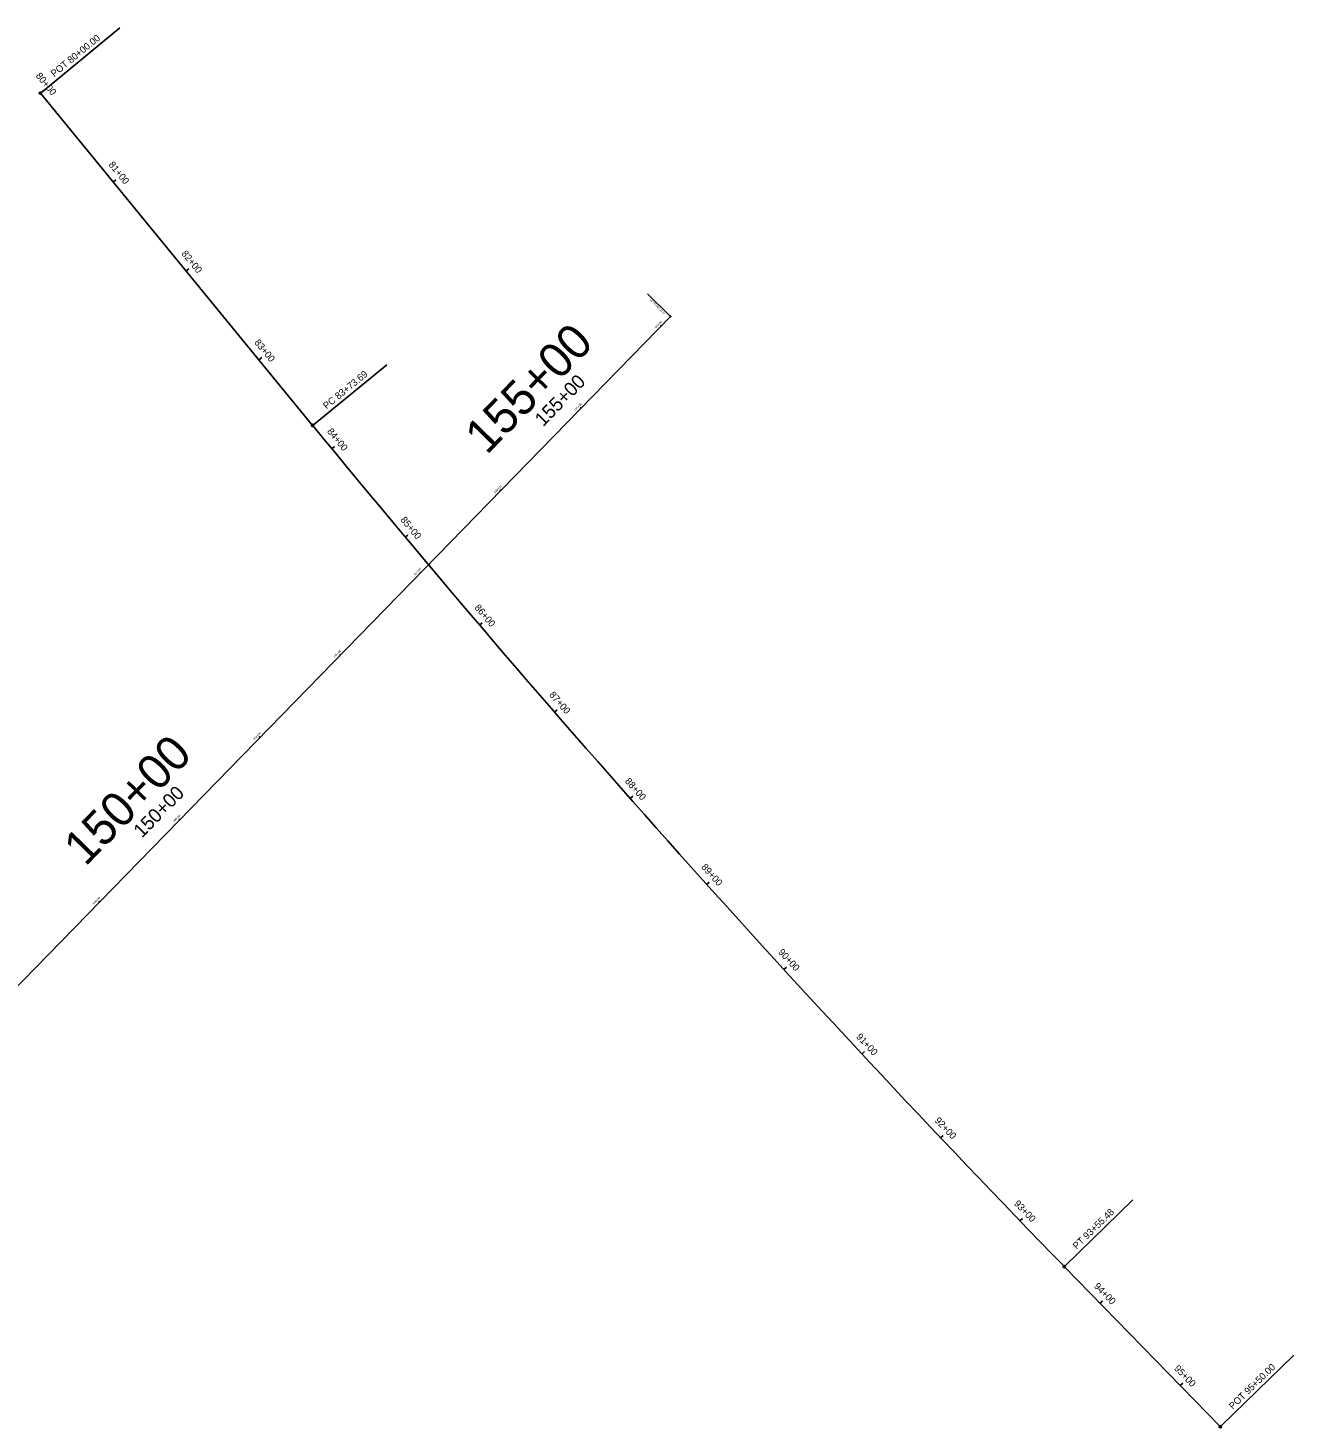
# Model space of a CAD drawing. Extents: x 2252491 to 2257126, y 13788370 to 13792743.
# Drawn here: x 2256024 to 2257126, y 13791525 to 13792743 of the extents above; entities that cross this region are included whole.
import ezdxf

# ---------------------------------------------------------------- set-up
doc = ezdxf.new("R2010")
doc.units = 0
for name, color, linetype in [('D_ALIGN_1', 7, 'Continuous'), ('D_ALIGN_ANNO_1', 7, 'Continuous'), ('D_ALIGN_ANNO_200_drn', 7, 'Continuous'), ('D_ALIGN_ANNO_DRN_300', 7, 'Continuous'), ('D_ALIGN_ANNO_FM725', 7, 'Continuous'), ('D_ALIGN_FM725', 7, 'Continuous')]:
    doc.layers.add(name, color=color, linetype=linetype)

msp = doc.modelspace()

# ---------------------------------------------------------------- linework, layer by layer
at = {"layer": 'D_ALIGN_1'}
msp.add_line((2255995.1, 13791888.8), (2256583.2, 13792491.8), dxfattribs=at)
at = {"layer": 'D_ALIGN_ANNO_1'}
for p, q in [((2256583, 13792492), (2256563.2, 13792511.4)), ((2256575.2, 13792483.6), (2256574.5, 13792484.2)), ((2256505.4, 13792412), (2256504.7, 13792412.6)), ((2256435.5, 13792340.4), (2256434.9, 13792341)), ((2256365.7, 13792268.8), (2256365.1, 13792269.4)), ((2256295.9, 13792197.2), (2256295.3, 13792197.8)), ((2256226.1, 13792125.6), (2256225.4, 13792126.3)), ((2256156.3, 13792054), (2256155.6, 13792054.7)), ((2256086.4, 13791982.4), (2256085.8, 13791983.1))]:
    msp.add_line(p, q, dxfattribs=at)
msp.add_circle((2256583.2, 13792491.8), 0.3, dxfattribs=at)
at = {"layer": 'D_ALIGN_ANNO_FM725'}
for p, q in [((2256035.9, 13792686.7), (2256104.3, 13792742.8)), ((2256035.1, 13792686.1), (2256037.4, 13792688)), ((2256098.5, 13792608.8), (2256100.8, 13792610.7)), ((2256161.9, 13792531.4), (2256164.2, 13792533.3)), ((2256225.2, 13792454.1), (2256227.6, 13792456)), ((2256272.7, 13792397.7), (2256336.5, 13792449.9)), ((2256288.6, 13792376.7), (2256291, 13792378.6)), ((2256352.5, 13792299.8), (2256354.8, 13792301.7)), ((2256417.1, 13792223.4), (2256419.4, 13792225.4)), ((2256482.3, 13792147.6), (2256484.6, 13792149.6)), ((2256548.2, 13792072.4), (2256550.5, 13792074.4)), ((2256614.7, 13791997.8), (2256617, 13791999.8)), ((2256681.9, 13791923.7), (2256684.1, 13791925.7)), ((2256749.8, 13791850.2), (2256752, 13791852.3)), ((2256818.2, 13791777.3), (2256820.4, 13791779.4)), ((2256926.7, 13791665.9), (2256985.6, 13791723.3)), ((2256887.3, 13791705.1), (2256889.5, 13791707.1)), ((2256957, 13791633.3), (2256959.2, 13791635.4)), ((2257062.4, 13791526.6), (2257125.7, 13791588.2)), ((2257026.8, 13791561.7), (2257028.9, 13791563.8))]:
    msp.add_line(p, q, dxfattribs=at)
for centre in [(2256035.1, 13792686.1), (2256271.9, 13792397.1), (2256925.9, 13791665.2), (2257061.7, 13791525.9)]:
    msp.add_circle(centre, 1, dxfattribs=at)
at = {"layer": 'D_ALIGN_FM725'}
for p, q in [((2256035.1, 13792686.1), (2256271.9, 13792397.1)), ((2256925.9, 13791665.2), (2257061.7, 13791525.9))]:
    msp.add_line(p, q, dxfattribs=at)
msp.add_arc((2265135.7, 13799659.8), 11459.2, 219.33034, 224.23927, dxfattribs=at)

# ---------------------------------------------------------------- texts
at = {"layer": 'D_ALIGN_ANNO_1'}
for s, rotation, p in [('POT 156+11.51', 135.7179, (2256578.7, 13792494.9)), ('156+00', 45.7179, (2256570.2, 13792481.1)), ('155+00', 45.7179, (2256500.4, 13792409.5)), ('154+00', 45.7179, (2256430.6, 13792337.9)), ('153+00', 45.7179, (2256360.8, 13792266.3)), ('152+00', 45.7179, (2256291, 13792194.7)), ('151+00', 45.7179, (2256221.2, 13792123.2)), ('150+00', 45.7179, (2256151.3, 13792051.6)), ('149+00', 45.7179, (2256081.5, 13791980))]:
    msp.add_text(s, height=1.8, rotation=rotation, dxfattribs=at).set_placement(p)
at = {"layer": 'D_ALIGN_ANNO_200_drn'}
for s, p in [('155+00', (2256472.5, 13792395.5)), ('150+00', (2256123.4, 13792037.6))]:
    msp.add_text(s, height=12, rotation=45.7179, dxfattribs=at).set_placement(p)
at = {"layer": 'D_ALIGN_ANNO_DRN_300'}
for s, p in [('155+00', (2256423.3, 13792370.8)), ('150+00', (2256074.2, 13792012.8))]:
    msp.add_text(s, height=30, rotation=45.7179, dxfattribs=at).set_placement(p)
at = {"layer": 'D_ALIGN_ANNO_FM725'}
for s, rotation, p in [('POT 80+00.00', 39.3303, (2256047.1, 13792699.8)), ('80+00', 309.3303, (2256030.6, 13792701)), ('81+00', 309.3303, (2256094, 13792623.7)), ('82+00', 309.3303, (2256157.4, 13792546.3)), ('83+00', 309.3303, (2256220.8, 13792469)), ('PC 83+73.69', 39.3303, (2256284, 13792410.8)), ('84+00', 309.4619, (2256284.1, 13792391.6)), ('85+00', 309.9619, (2256347.9, 13792314.7)), ('86+00', 310.4619, (2256412.3, 13792238.3)), ('87+00', 310.9619, (2256477.4, 13792162.4)), ('88+00', 311.4619, (2256543.2, 13792087.2)), ('89+00', 311.9619, (2256609.6, 13792012.5)), ('90+00', 312.4619, (2256676.6, 13791938.4)), ('91+00', 312.9619, (2256744.4, 13791864.8)), ('92+00', 313.4619, (2256812.7, 13791791.9)), ('93+00', 313.9619, (2256881.7, 13791719.6)), ('PT 93+55.48', 44.2393, (2256936.7, 13791679.9)), ('94+00', 314.2393, (2256951.3, 13791647.8)), ('95+00', 314.2393, (2257021, 13791576.2)), ('POT 95+50.00', 44.2393, (2257072.5, 13791540.6))]:
    msp.add_text(s, height=6, rotation=rotation, dxfattribs=at).set_placement(p)

doc.saveas('drawing.dxf')
